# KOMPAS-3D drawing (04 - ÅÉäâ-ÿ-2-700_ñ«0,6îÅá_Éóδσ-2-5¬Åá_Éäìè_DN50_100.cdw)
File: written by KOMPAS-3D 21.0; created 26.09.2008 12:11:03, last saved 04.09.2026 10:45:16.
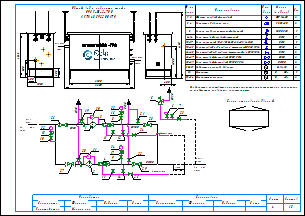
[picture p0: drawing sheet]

Sheets 1-2: A3, landscape

Document properties: Наименование: Макро:21; Автор: RaskoAdmin; Форматы листов документа: 2xA3; Полное имя файла: \\UR38nt01\Departments\КТО\КБ ПУРДГ\Заявки\Прайс-лист на типовые шкафы ГРПШ\ПРДГ_стандарт_20_03_2026\ПРДГ с РДНК\ПРДГ-Ш-2-700_до0,6МПа_Рвых-2-5кПа_РДНК_DN50_100.cdw

Title block, sheet 1: Наименование: Пункт учета газа / ПУГ-Ш-400-Р / ЛГТИ.485922.001ТУ; designation: ЛГТИ.03.4411141; sheet number: 1; Количество листов документа: 2; organisation: ООО "ЭЛЬСТЕР Газэлектроника"; Форматы листов документа: A3; stored path: C:\Рабочие документы\Компас\ПУГ\Схема.cdw; Разработал: Устинов; Проверил: Кошкин; Утвердил: Кошкин
Title block, sheet 2: sheet number: 2; stored path: D:\Рабочие документы\Заявки\ПУРДГ\ПУРДГ-ШУЭО-2-100-Р 4411220.cdw; designation, second copy: ЛГТИ.03.4411141-

Views: Вид 1, Вид 2
Referenced files: wcvoit.frw
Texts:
  Normal
  Вход
  газа
  PDI
  Выход
  Р=     кПа
  DN100
  DN50
  DN20
  Импульс DN15
  ≥5DN
  HYSWLongFangSong
  № на
  схеме
  Усл.
  обозн.
  Марка
  (модель)
  Кол.
  Фильтр газовый фланцевый
  ФГ 16-50
  Регулятор давления газа
  РДНК-50
  Клапан предохранительный сбросной
  КПС DN20
  Кран шаровой газовый латунный
  DN15
  Кран кнопочный VE-РАСКО-НЗ-1,6-G1/2-М20
  Кран шаровой "под приварку" штуцерный DN20 PN16
  Кран шаровой "под приварку" штуцерный п/п DN15 PN16
  Кран шаровой фланцевый DN50 PN16
  Кран шаровой фланцевый DN100 PN16
  Индикатор перепада давления
  Delta 15
  Манометр
  Манометр-напоромер
  0...     МПа
  0...     кПа
  Общий вид и габариты шкафа
  ПРДГ-Ш-2-700
  Выход газа
  Вход газа
  Схема открывания дверей
  logo-rasko-ge.png
  Предприятие изготовитель может заменять комплектующие на аналогичные,
  не ухудшающие заявленных характеристик.
  Р=        МПа
  Должность
  Конструктор
  Фамилия
  Подпись
  Дата
  Согласовано
  Максимкин
  Лист
  Листов
  POLYLINE_STYLE_0.18_RGB_0_0_0
  POLYLINE_STYLE_0.50_RGB_0_0_0
  POLYLINE_STYLE_0.34_RGB_0_0_0
  PHANTOM_RGB_0_0_0_SC_1_THICK_0.18
  K5LT_THIN_RGB_0_0_0_THICK_0.18
  K5LT32769_RGB_0_0_0_THICK_0.18
  K5LT12_RGB_0_0_0_SC_1_THICK_0.18
  K5LT_DASHED_RGB_0_0_0_SC_1_THICK_0.18
  ACISOTGL_RGB_0_0_0_SC_0.8_THICK_0.25
  CONTINUOUS_RGB_0_127_31_THICK_0.3
  CONTINUOUS_RGB_0_0_255_THICK_0.35
  CONTINUOUS_RGB_255_0_0_THICK_0.35
  POLYLINE_STYLE_0.25_RGB_0_0_0
  CONTINUOUS_RGB_0_0_0_THICK_0.5
  POLYLINE_STYLE_0.35_RGB_0_0_255
  CONTINUOUS_RGB_0_0_0_THICK_0.4
  CONTINUOUS_RGB_0_0_0_THICK_0.35
  Без оформления
Dimensions and other numbers on the sheet: 1; 2; 3; 4; 5; 10; 27; 28; 29; 23; 8; 12; 19; 20; 21; 22; 25; 24; 30; 31; 15; 16; 26; 6; 7; 11; 14; 13; 33; 1, 2; 3, 4; 6-14; 9; 15-17; 18-23; 24-25; 26-27; 28-29; 30-31; 32; 33-34; 400; 1050; 500; 305; 2300; 1565; 2600; 17; 34; 1000; 4130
